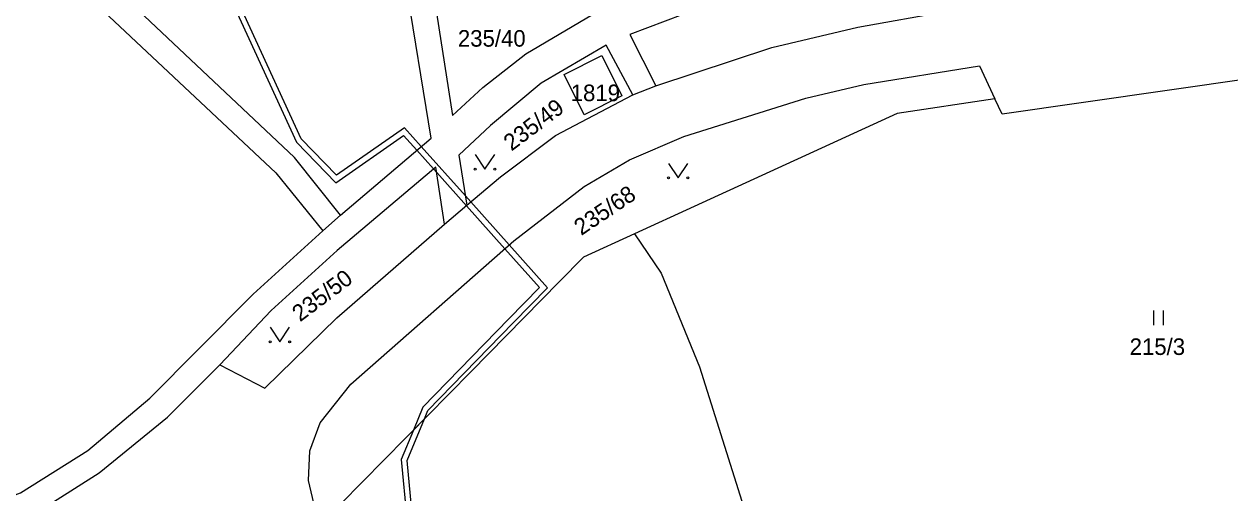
# Model space of a CAD drawing. Extents: x -680203 to -673936, y -1102717 to -1093650.
# Drawn here: x -679395.6 to -679271.8, y -1098331.2 to -1098283.1 of the extents above; entities that cross this region are included whole.
import ezdxf

# ---------------------------------------------------------------- set-up
doc = ezdxf.new("R2010")
doc.units = 0
for name, color, linetype in [('SOxxxxxx_Koleje_hlavní_body_Popis10', 7, 'Continuous'), ('SOxxxxxx_Koleje_LN_parametry_Popis10', 7, 'Continuous'), ('SOxxxxxx_Osa_bod_P', 7, 'Continuous'), ('x_prac', 7, 'Continuous')]:
    doc.layers.add(name, color=color, linetype=linetype)

msp = doc.modelspace()

# ---------------------------------------------------------------- linework, layer by layer
at = {"layer": 'SOxxxxxx_Koleje_hlavní_body_Popis10'}
for p, q in [((-679279.62, -1098313.99), (-679279.62, -1098312.49)), ((-679278.62, -1098313.99), (-679278.62, -1098312.49))]:
    msp.add_line(p, q, dxfattribs=at)
for points in [[(-679349.28, -1098296.51), (-679348.28, -1098298.01), (-679347.28, -1098296.51)], [(-679329.45, -1098297.4), (-679328.45, -1098298.9), (-679327.45, -1098297.4)], [(-679370.33, -1098314.21), (-679369.33, -1098315.71), (-679368.33, -1098314.21)]]:
    msp.add_lwpolyline(points, dxfattribs=at)
for centre in [(-679349.28, -1098298.01), (-679347.28, -1098298.01), (-679329.45, -1098298.9), (-679327.45, -1098298.9), (-679370.33, -1098315.71), (-679368.33, -1098315.71)]:
    msp.add_circle(centre, 0.1, dxfattribs=at)
at = {"layer": 'SOxxxxxx_Koleje_LN_parametry_Popis10'}
for points in [[(-679374.1, -1098281.18), (-679367.64, -1098295.23), (-679363.59, -1098299.4), (-679356.63, -1098294.55), (-679355.28, -1098296.06), (-679353.56, -1098297.98), (-679353.24, -1098298.33), (-679350.19, -1098301.75), (-679346.25, -1098306.16), (-679342.69, -1098310.14), (-679345.82, -1098313.34), (-679354.66, -1098322.42), (-679355.62, -1098324.76), (-679354.5, -1098323.62), (-679354.14, -1098322.76), (-679345.4, -1098313.76), (-679341.87, -1098310.16), (-679345.8, -1098305.76), (-679349.74, -1098301.36), (-679350.29, -1098300.73), (-679354.82, -1098295.67), (-679356.53, -1098293.75), (-679363.51, -1098298.62), (-679367.14, -1098294.89), (-679373.54, -1098280.98)], [(-679355.71, -1098333.73), (-679356.26, -1098327.88), (-679354.5, -1098323.62), (-679355.62, -1098324.76), (-679356.88, -1098327.78), (-679356.29, -1098333.87)]]:
    msp.add_lwpolyline(points, dxfattribs=at)
at = {"layer": 'x_prac'}
for p, q in [((-679333.09, -1098290.37), (-679330.75, -1098289.45)), ((-679352.42, -1098303.65), (-679350.14, -1098301.7)), ((-679364.94, -1098304.34), (-679363.11, -1098302.71))]:
    msp.add_line(p, q, dxfattribs=at)
for points in [[(-679363.11, -1098302.71), (-679367.84, -1098296.79), (-679393.89, -1098272.22), (-679394.85, -1098270.45), (-679395.12, -1098268.73), (-679389.87, -1098266.4), (-679386.46, -1098265.48), (-679358.42, -1098261.61), (-679357.58, -1098267.22)], [(-679435.9, -1098333.97), (-679417.89, -1098288.06), (-679409.5, -1098279.65), (-679403.91, -1098274.56), (-679397.57, -1098270.19), (-679397.41, -1098273.5), (-679401.35, -1098284.06), (-679398.94, -1098284.91), (-679395.13, -1098274.55), (-679369.75, -1098298.38), (-679364.94, -1098304.34)], [(-679353.83, -1098278.2), (-679351.62, -1098292.5), (-679348.51, -1098289.63), (-679344.1, -1098286.15), (-679337.23, -1098282.12), (-679338.49, -1098276)], [(-679300.8, -1098281.8), (-679301.66, -1098277.08), (-679319.67, -1098279.5), (-679326.16, -1098281.44), (-679333.42, -1098284.18), (-679330.75, -1098289.45)], [(-679363.11, -1098302.71), (-679353.82, -1098294.82), (-679356.45, -1098278.65)], [(-679330.75, -1098289.45), (-679318.83, -1098285.5), (-679310, -1098283.42), (-679300.8, -1098281.8)], [(-679333.09, -1098290.37), (-679335.84, -1098285.27), (-679342.52, -1098289.16), (-679347.71, -1098293.51), (-679350.96, -1098296.56), (-679350.14, -1098301.7)], [(-679338.11, -1098292.41), (-679340.14, -1098288.3), (-679336.3, -1098286.33), (-679334.25, -1098290.49), (-679338.11, -1098292.41)], [(-679365.29, -1098334.59), (-679366.39, -1098329.93), (-679366.27, -1098326.88), (-679365.2, -1098324.03), (-679362.04, -1098320.05), (-679345.32, -1098305.34), (-679338.11, -1098299.77), (-679333.44, -1098297.04), (-679327.87, -1098294.66), (-679315.36, -1098290.71), (-679309.39, -1098289.32), (-679297.54, -1098287.41), (-679295.95, -1098290.78)], [(-679269.68, -1098288.69), (-679295.2, -1098292.35), (-679295.95, -1098290.78)], [(-679350.14, -1098301.7), (-679346.69, -1098298.78), (-679341.05, -1098294.56), (-679333.09, -1098290.37)], [(-679295.95, -1098290.78), (-679305.98, -1098292.29), (-679326.82, -1098301.83), (-679332.94, -1098304.63)], [(-679352.42, -1098303.65), (-679353.33, -1098297.78), (-679363.44, -1098306.33), (-679370.23, -1098312.49), (-679375.5, -1098318.09)], [(-679435.9, -1098333.97), (-679428.84, -1098334.78), (-679422.26, -1098335.39), (-679414.73, -1098335.57), (-679409.6, -1098335.28), (-679403.93, -1098334.13), (-679395.95, -1098331.19), (-679389.06, -1098326.87), (-679382.68, -1098321.49), (-679377.68, -1098316.47), (-679372.06, -1098310.82), (-679364.94, -1098304.34)], [(-679375.5, -1098318.09), (-679370.89, -1098320.47), (-679363.48, -1098313.26), (-679352.42, -1098303.65)], [(-679332.94, -1098304.63), (-679338.17, -1098307.02), (-679340.62, -1098309.51), (-679349.74, -1098318.78), (-679365.29, -1098334.59)], [(-679332.94, -1098304.63), (-679330.21, -1098308.66), (-679326.25, -1098318.27), (-679315.79, -1098351.49), (-679312.78, -1098361.03)], [(-679429.43, -1098337.41), (-679422.63, -1098337.98), (-679414.84, -1098338.3), (-679413.1, -1098343.14), (-679409.9, -1098342.89), (-679409.12, -1098337.85), (-679403.23, -1098336.72), (-679394.73, -1098333.49), (-679387.89, -1098329.16), (-679380.88, -1098323.43), (-679375.5, -1098318.09)]]:
    msp.add_lwpolyline(points, dxfattribs=at)

# ---------------------------------------------------------------- texts
at = {"layer": 'SOxxxxxx_Osa_bod_P'}
for s, p in [('235/40', (-679351.06, -1098285.43)), ('1819', (-679339.48, -1098291.02)), ('215/3', (-679282.11, -1098317.06))]:
    msp.add_text(s, height=1.7, dxfattribs=at).set_placement(p)
for s, rotation, p in [('235/49', 37, (-679345.56, -1098296.2)), ('235/68', 34, (-679338.4, -1098304.86)), ('235/50', 37, (-679367.26, -1098313.72))]:
    msp.add_text(s, height=1.7, rotation=rotation, dxfattribs=at).set_placement(p)

doc.saveas('drawing.dxf')
